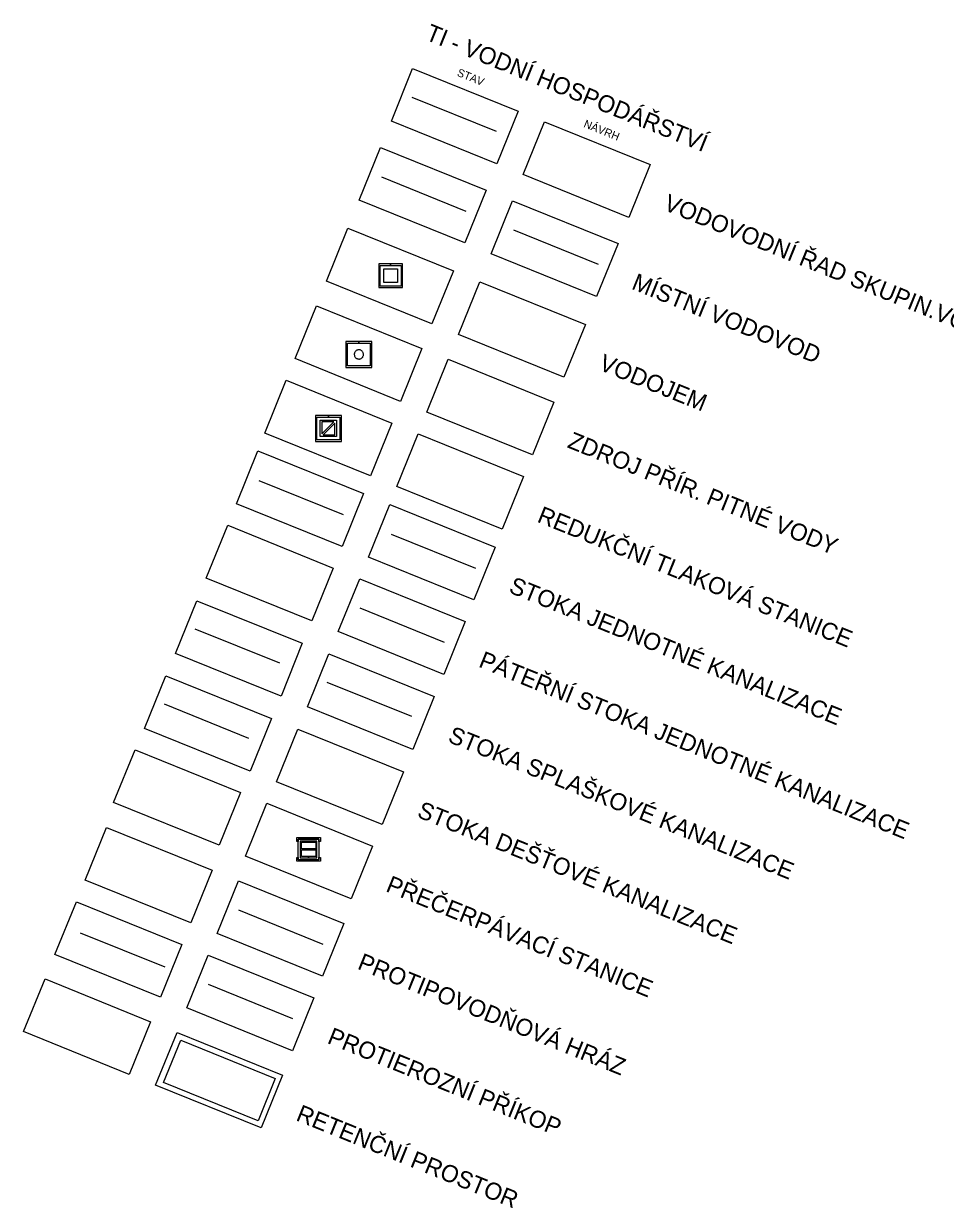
# Model space of a CAD drawing. Extents: x -522763 to -519637, y -1191176 to -1188936.
# Drawn here: x -521891 to -521081, y -1190479 to -1189438 of the extents above; entities that cross this region are included whole.
import ezdxf

# ---------------------------------------------------------------- set-up
doc = ezdxf.new("R2010")
doc.units = 0
for name, color, linetype in [('Implicitní', 7, 'Continuous'), ('kan_pater_j_n', 7, 'Continuous'), ('kan_stoka_j_n', 7, 'Continuous'), ('kan_stoka_j_s', 7, 'Continuous'), ('kan_stoka_s_n', 7, 'Continuous'), ('kan_stoka_s_s', 7, 'Continuous'), ('ložisk_nerost', 7, 'Continuous'), ('pe_prikop_n', 7, 'Continuous'), ('pe_prikop_s', 7, 'Continuous'), ('pp_hraz_n', 7, 'Continuous'), ('ret_prostor_n', 7, 'Continuous'), ('zast_HD_s', 7, 'Continuous')]:
    doc.layers.add(name, color=color, linetype=linetype)

msp = doc.modelspace()

# ---------------------------------------------------------------- linework, layer by layer
at = {"layer": 'Implicitní'}
for p, q in [((-521549.9, -1189502.4), (-521475.8, -1189532.5)), ((-521576.4, -1189572.6), (-521502.3, -1189602.7)), ((-521460.4, -1189619), (-521386.2, -1189649.1))]:
    msp.add_line(p, q, dxfattribs=at)
for points in [[(-521549.1, -1189477.2), (-521456.4, -1189514.8), (-521475.2, -1189561.1), (-521567.8, -1189523.5)], [(-521433.2, -1189524.2), (-521340.5, -1189561.7), (-521359.3, -1189608.1), (-521452, -1189570.5)], [(-521577.2, -1189546.7), (-521484.6, -1189584.3), (-521503.3, -1189630.6), (-521596, -1189593)], [(-521461.4, -1189593.7), (-521368.7, -1189631.2), (-521387.5, -1189677.6), (-521480.2, -1189640)], [(-521606, -1189617.6), (-521513.3, -1189655.2), (-521532.1, -1189701.5), (-521624.7, -1189664)], [(-521490.1, -1189664.6), (-521397.4, -1189702.1), (-521416.2, -1189748.5), (-521508.9, -1189710.9)], [(-521633.6, -1189685.9), (-521541, -1189723.4), (-521559.7, -1189769.8), (-521652.4, -1189732.2)], [(-521517.8, -1189732.8), (-521425.1, -1189770.4), (-521443.9, -1189816.7), (-521536.6, -1189779.2)], [(-521660.1, -1189751.2), (-521567.4, -1189788.8), (-521586.2, -1189835.1), (-521678.9, -1189797.6)], [(-521544.3, -1189798.2), (-521451.6, -1189835.7), (-521470.4, -1189882.1), (-521563.1, -1189844.5)], [(-521685, -1189813.2), (-521592.3, -1189850.8), (-521611.1, -1189897.1), (-521703.8, -1189859.6)], [(-521569.1, -1189860.2), (-521476.5, -1189897.8), (-521495.3, -1189944.1), (-521587.9, -1189906.5)], [(-521711.5, -1189878.6), (-521618.8, -1189916.2), (-521637.6, -1189962.5), (-521730.3, -1189924.9)], [(-521595.6, -1189925.6), (-521503, -1189963.1), (-521521.7, -1190009.5), (-521614.4, -1189971.9)], [(-521738.7, -1189944.8), (-521646, -1189982.2), (-521664.7, -1190028.6), (-521757.4, -1189991.1)], [(-521622.8, -1189991.6), (-521530.1, -1190029.1), (-521548.8, -1190075.4), (-521641.5, -1190038)], [(-521765.8, -1190010.7), (-521673, -1190048.2), (-521691.8, -1190094.5), (-521784.5, -1190057.1)], [(-521649.9, -1190057.6), (-521557.1, -1190095), (-521575.9, -1190141.4), (-521668.6, -1190103.9)], [(-521792.9, -1190075.8), (-521700.3, -1190113.3), (-521719, -1190159.7), (-521811.7, -1190122.1)], [(-521677.1, -1190122.7), (-521584.4, -1190160.3), (-521603.2, -1190206.6), (-521695.9, -1190169.1)], [(-521817.9, -1190143.9), (-521725.2, -1190181.4), (-521744, -1190227.8), (-521836.7, -1190190.2)], [(-521702.1, -1190190.8), (-521609.4, -1190228.4), (-521628.2, -1190274.7), (-521720.8, -1190237.1)], [(-521844.4, -1190209.2), (-521751.7, -1190246.8), (-521770.5, -1190293.1), (-521863.2, -1190255.6)], [(-521728.6, -1190256.2), (-521635.9, -1190293.7), (-521654.7, -1190340.1), (-521747.3, -1190302.5)], [(-521871.9, -1190277), (-521779.2, -1190314.6), (-521798, -1190360.9), (-521890.7, -1190323.3)], [(-521756, -1190324), (-521663.4, -1190361.5), (-521682.1, -1190407.9), (-521774.8, -1190370.3)]]:
    msp.add_lwpolyline(points, close=True, dxfattribs=at)
at = {"layer": 'kan_pater_j_n'}
msp.add_line((-521595.5, -1189951.2), (-521521.3, -1189981.2), dxfattribs=at)
at = {"layer": 'kan_stoka_j_n'}
msp.add_line((-521567.9, -1189886.3), (-521493.8, -1189916.3), dxfattribs=at)
at = {"layer": 'kan_stoka_j_s'}
msp.add_line((-521684.2, -1189839.1), (-521610, -1189869.2), dxfattribs=at)
at = {"layer": 'kan_stoka_s_n'}
msp.add_line((-521624.4, -1190016.4), (-521550.2, -1190046.3), dxfattribs=at)
at = {"layer": 'kan_stoka_s_s'}
for p, q in [((-521740.3, -1189969.5), (-521666.1, -1189999.5)), ((-521767.4, -1190035.5), (-521693.2, -1190065.5))]:
    msp.add_line(p, q, dxfattribs=at)
at = {"layer": 'ložisk_nerost'}
for p, q in [((-521630.3, -1189800.7), (-521630.3, -1189786.3)), ((-521630.3, -1189786.3), (-521623.1, -1189786.3)), ((-521623.1, -1189787.7), (-521628.8, -1189787.7)), ((-521628.8, -1189787.7), (-521628.8, -1189798.2)), ((-521628.8, -1189798.2), (-521618.3, -1189787.7)), ((-521617.3, -1189788.8), (-521627.8, -1189799.2)), ((-521623.1, -1189786.3), (-521623.1, -1189787.7)), ((-521623, -1189787.7), (-521623, -1189786.3)), ((-521623, -1189786.3), (-521615.9, -1189786.3)), ((-521618.3, -1189787.7), (-521623, -1189787.7)), ((-521617.3, -1189799.2), (-521617.3, -1189788.8)), ((-521615.9, -1189786.3), (-521615.9, -1189800.7)), ((-521623.1, -1189800.7), (-521630.3, -1189800.7)), ((-521627.8, -1189799.2), (-521623.1, -1189799.2)), ((-521623.1, -1189799.2), (-521623.1, -1189800.7)), ((-521623, -1189800.7), (-521623, -1189799.2)), ((-521623, -1189799.2), (-521617.3, -1189799.2)), ((-521615.9, -1189800.7), (-521623, -1189800.7))]:
    msp.add_line(p, q, dxfattribs=at)
for points in [[(-521596.4, -1189717.1), (-521607.8, -1189717.1), (-521607.7, -1189740), (-521584.8, -1189739.9), (-521584.9, -1189717), (-521596.3, -1189717.1)], [(-521606.4, -1189718.5), (-521586.3, -1189718.5), (-521586.3, -1189738.5), (-521606.3, -1189738.6), (-521606.4, -1189718.5)], [(-521596.3, -1189718.5), (-521586.3, -1189718.5), (-521586.3, -1189738.5), (-521606.3, -1189738.6), (-521606.4, -1189718.5), (-521596.4, -1189718.5)], [(-521596.4, -1189718.5), (-521596.4, -1189717.1)], [(-521596.3, -1189717.1), (-521596.3, -1189718.5)], [(-521592.2, -1189728.5), (-521592.3, -1189728), (-521592.4, -1189727.5), (-521592.5, -1189727), (-521592.8, -1189726.5), (-521593, -1189726.1), (-521593.4, -1189725.7), (-521593.7, -1189725.4), (-521594.2, -1189725.1), (-521594.6, -1189724.8), (-521595.1, -1189724.6), (-521595.6, -1189724.5), (-521596.1, -1189724.4), (-521596.6, -1189724.5), (-521597.1, -1189724.5), (-521597.6, -1189724.7), (-521598.1, -1189724.9), (-521598.6, -1189725.1), (-521599, -1189725.4), (-521599.3, -1189725.8), (-521599.7, -1189726.2), (-521599.9, -1189726.6), (-521600.1, -1189727.1), (-521600.3, -1189727.6), (-521600.4, -1189728.1), (-521600.4, -1189728.6), (-521600.3, -1189729.1), (-521600.2, -1189729.6), (-521600.1, -1189730.1), (-521599.8, -1189730.6), (-521599.5, -1189731), (-521599.2, -1189731.4), (-521598.8, -1189731.7), (-521598.4, -1189732), (-521597.9, -1189732.2), (-521597.4, -1189732.4), (-521596.9, -1189732.5), (-521596.4, -1189732.6), (-521595.9, -1189732.6), (-521595.4, -1189732.5), (-521594.9, -1189732.3), (-521594.4, -1189732.1), (-521594, -1189731.9), (-521593.6, -1189731.5), (-521593.2, -1189731.2), (-521592.9, -1189730.8), (-521592.7, -1189730.3), (-521592.5, -1189729.8), (-521592.3, -1189729.3), (-521592.3, -1189728.8), (-521592.2, -1189728.5)], [(-521623.1, -1189782.1), (-521634.5, -1189782), (-521634.5, -1189804.9), (-521611.7, -1189804.9), (-521611.6, -1189782.1), (-521623.1, -1189782.1)], [(-521633.1, -1189783.5), (-521613, -1189783.5), (-521613.1, -1189803.5), (-521633.1, -1189803.5), (-521633.1, -1189783.5)], [(-521623.1, -1189783.5), (-521613, -1189783.5), (-521613.1, -1189803.5), (-521633.1, -1189803.5), (-521633.1, -1189783.5), (-521623.1, -1189783.5)], [(-521623.1, -1189782.1), (-521623.1, -1189783.5)], [(-521623.1, -1189783.5), (-521623.1, -1189782.1)]]:
    msp.add_lwpolyline(points, dxfattribs=at)
at = {"layer": 'pe_prikop_n'}
msp.add_line((-521728.6, -1190281.7), (-521654.5, -1190311.8), dxfattribs=at)
at = {"layer": 'pe_prikop_s'}
msp.add_line((-521841, -1190236.5), (-521766.8, -1190266.5), dxfattribs=at)
at = {"layer": 'pp_hraz_n'}
msp.add_line((-521702.1, -1190216.3), (-521628, -1190246.4), dxfattribs=at)
at = {"layer": 'ret_prostor_n'}
msp.add_lwpolyline([(-521752.7, -1190330.9), (-521669.7, -1190364.5), (-521684.7, -1190401.7), (-521767.8, -1190368)], close=True, dxfattribs=at)
at = {"layer": 'zast_HD_s'}
for points in [[(-521568.4, -1189649), (-521578.8, -1189649), (-521578.8, -1189669.8), (-521558, -1189669.8), (-521558, -1189649), (-521568.4, -1189649)], [(-521577.5, -1189650.3), (-521559.3, -1189650.3), (-521559.3, -1189668.5), (-521577.5, -1189668.5), (-521577.5, -1189650.3)], [(-521568.4, -1189650.3), (-521559.3, -1189650.3), (-521559.3, -1189668.5), (-521577.5, -1189668.5), (-521577.5, -1189650.3), (-521568.4, -1189650.3)], [(-521574.4, -1189653.4), (-521562.4, -1189653.4), (-521562.4, -1189665.4), (-521574.4, -1189665.4), (-521574.4, -1189653.4)], [(-521568.4, -1189649), (-521568.4, -1189650.3)], [(-521568.4, -1189650.3), (-521568.4, -1189649)], [(-521650.9, -1190156.2), (-521650.9, -1190152.9)], [(-521650.9, -1190152.9), (-521633.5, -1190152.9)], [(-521649.7, -1190154.2), (-521631.4, -1190154.2), (-521631.4, -1190172.4), (-521649.6, -1190172.4), (-521649.7, -1190154.2)], [(-521633.5, -1190154.2), (-521649.7, -1190154.2), (-521649.7, -1190156.2)], [(-521640.5, -1190156), (-521647.8, -1190156)], [(-521647.8, -1190156), (-521647.8, -1190170.6)], [(-521633.2, -1190156), (-521640.5, -1190156)], [(-521640.5, -1190156), (-521640.5, -1190157)], [(-521640.5, -1190157), (-521640.5, -1190156)], [(-521633.5, -1190152.9), (-521630.1, -1190152.9), (-521630.1, -1190156.2)], [(-521631.4, -1190156.2), (-521631.4, -1190154.2), (-521633.5, -1190154.2)], [(-521633.2, -1190170.6), (-521633.2, -1190156)], [(-521649.7, -1190156.2), (-521650.9, -1190156.2)], [(-521646.8, -1190162.8), (-521646.8, -1190157)], [(-521646.8, -1190157), (-521640.5, -1190157)], [(-521634.2, -1190162.8), (-521646.8, -1190162.8)], [(-521640.5, -1190169.6), (-521646.8, -1190169.6), (-521646.8, -1190163.8)], [(-521646.8, -1190163.8), (-521634.2, -1190163.8)], [(-521640.5, -1190157), (-521634.2, -1190157)], [(-521634.2, -1190163.8), (-521634.2, -1190169.6), (-521640.5, -1190169.6)], [(-521634.2, -1190157), (-521634.2, -1190162.8)], [(-521630.1, -1190156.2), (-521631.4, -1190156.2)], [(-521647.6, -1190173.7), (-521650.9, -1190173.7), (-521650.9, -1190170.4)], [(-521650.9, -1190170.4), (-521649.6, -1190170.4)], [(-521649.6, -1190170.4), (-521649.6, -1190172.4), (-521633.5, -1190172.4)], [(-521647.8, -1190170.6), (-521640.5, -1190170.6)], [(-521630.1, -1190170.4), (-521630.1, -1190173.7), (-521647.6, -1190173.7)], [(-521640.5, -1190170.6), (-521640.5, -1190169.6)], [(-521640.5, -1190169.6), (-521640.5, -1190170.6)], [(-521640.5, -1190170.6), (-521633.2, -1190170.6)], [(-521633.5, -1190172.4), (-521631.4, -1190172.4), (-521631.4, -1190170.4)], [(-521631.4, -1190170.4), (-521630.1, -1190170.4)]]:
    msp.add_lwpolyline(points, dxfattribs=at)

# ---------------------------------------------------------------- texts
at = {"layer": 'Implicitní'}
for s, height, rotation, p in [('TI - VODNÍ HOSPODÁŘSTVÍ', 15, 337.9379, (-521538.7, -1189451.7)), ('STAV', 7, 337.9379, (-521510.7, -1189483.6)), ('NÁVRH', 7, 337.9379, (-521399.5, -1189528.6)), ('VODOVODNÍ ŘAD SKUPIN.VODOVODU', 15, 337.9379, (-521329.6, -1189601.2)), ('MÍSTNÍ VODOVOD', 15, 337.9379, (-521357.7, -1189670.7)), ('VODOJEM', 15, 337.9379, (-521386.5, -1189741.6)), ('ZDROJ PŘÍR. PITNÉ VODY', 15, 337.9379, (-521414.1, -1189809.9)), ('REDUKČNÍ TLAKOVÁ STANICE', 15, 337.9379, (-521440.6, -1189875.3)), ('STOKA JEDNOTNÉ KANALIZACE', 15, 337.9379, (-521465.5, -1189937.3)), ('PÁTEŘNÍ STOKA JEDNOTNÉ KANALIZACE', 15, 337.9379, (-521492, -1190002.6)), ('STOKA SPLAŠKOVÉ KANALIZACE', 15, 337.9994, (-521519, -1190068.6)), ('STOKA DEŠŤOVÉ KANALIZACE', 15, 337.9994, (-521546.1, -1190134.5)), ('PŘEČERPÁVACÍ STANICE', 15, 337.9379, (-521573.5, -1190199.8)), ('PROTIPOVODŇOVÁ HRÁZ', 15, 337.9379, (-521598.4, -1190267.9)), ('PROTIEROZNÍ PŘÍKOP', 15, 337.9379, (-521624.9, -1190333.2)), ('RETENČNÍ PROSTOR', 15, 337.9379, (-521652.4, -1190401))]:
    msp.add_text(s, height=height, rotation=rotation, dxfattribs=at).set_placement(p)

doc.saveas('drawing.dxf')
